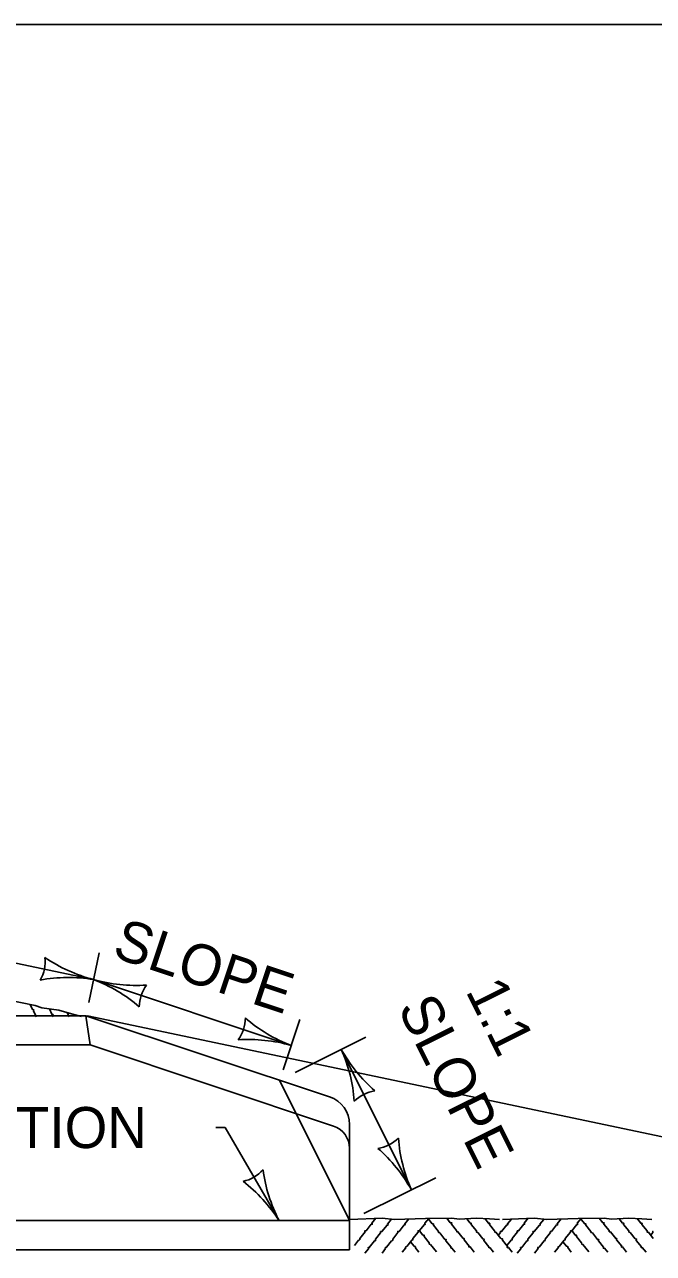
# Model space of a CAD drawing. Extents: x 49991.4 to 50021, y 49987.6 to 50011.4.
# Drawn here: x 50005.853 to 50006.771, y 49997.203 to 49998.999 of the extents above; entities that cross this region are included whole.
import ezdxf

# ---------------------------------------------------------------- set-up
doc = ezdxf.new("R2010")
doc.units = 0
for name, color, linetype in [('Level 1', 7, 'Continuous'), ('Level 2', 7, 'Continuous'), ('Level 3', 7, 'Continuous'), ('Level 4', 7, 'Continuous')]:
    doc.layers.add(name, color=color, linetype=linetype)

msp = doc.modelspace()

# ---------------------------------------------------------------- linework, layer by layer
at = {"layer": 'Level 1'}
for p, q in [((50003.702, 49997.5504), (50005.9421, 49997.5504)), ((50005.9421, 49997.5504), (50006.2981, 49997.4318)), ((50006.3273, 49997.3911), (50006.3273, 49997.208)), ((50006.3273, 49997.208), (50003.702, 49997.208))]:
    msp.add_line(p, q, dxfattribs=at)
msp.add_lwpolyline([(49999.3835, 49998.9992), (50016.7501, 49998.9992), (50016.7501, 49987.7988), (49999.3835, 49987.7988)], close=True, dxfattribs=at)
for points in [[(50005.7214, 49997.5944), (50005.7679, 49997.5866), (50005.785, 49997.5809), (50005.83, 49997.5731), (50005.8678, 49997.5653), (50005.8779, 49997.5617), (50005.9026, 49997.5584), (50005.9212, 49997.5532), (50005.9355, 49997.5494)], [(50005.8697, 49997.5486), (50005.8653, 49997.5572), (50005.866, 49997.559), (50005.8642, 49997.5593), (50005.8606, 49997.5668)], [(50005.8943, 49997.5486), (50005.8935, 49997.5506), (50005.8942, 49997.5522), (50005.8923, 49997.5526), (50005.8888, 49997.5602)], [(50005.9177, 49997.5486), (50005.9146, 49997.5552)], [(50006.3278, 49997.2526), (50006.375, 49997.2545), (50006.3929, 49997.2526), (50006.4385, 49997.2541), (50006.4769, 49997.2543), (50006.4876, 49997.2529), (50006.5126, 49997.2545), (50006.5318, 49997.2535), (50006.5465, 49997.2526)], [(50006.3658, 49997.2543), (50006.3598, 49997.2471), (50006.3605, 49997.2455), (50006.359, 49997.2455), (50006.3516, 49997.2361), (50006.3496, 49997.2361), (50006.35, 49997.2345), (50006.3422, 49997.2249), (50006.3422, 49997.2229), (50006.3406, 49997.2225), (50006.3344, 49997.2145)], [(50006.3882, 49997.2525), (50006.3827, 49997.2459), (50006.3836, 49997.2443), (50006.3821, 49997.2443), (50006.3746, 49997.2349), (50006.3726, 49997.2349), (50006.3728, 49997.2331), (50006.3652, 49997.2235), (50006.3652, 49997.2215), (50006.3636, 49997.2211), (50006.3562, 49997.2115), (50006.3545, 49997.2115), (50006.3548, 49997.2095), (50006.3496, 49997.2033)], [(50006.4139, 49997.2533), (50006.4079, 49997.246), (50006.4086, 49997.2445), (50006.4072, 49997.2445), (50006.3998, 49997.2351), (50006.3977, 49997.2351), (50006.398, 49997.2333), (50006.3905, 49997.2237), (50006.3905, 49997.222), (50006.3887, 49997.2213), (50006.3815, 49997.2119), (50006.3796, 49997.2117), (50006.38, 49997.21), (50006.3748, 49997.2034)], [(50006.4433, 49997.2541), (50006.4373, 49997.2469), (50006.438, 49997.2454), (50006.4367, 49997.2454), (50006.4292, 49997.2361), (50006.4274, 49997.2361), (50006.4276, 49997.2341), (50006.4199, 49997.2245), (50006.4199, 49997.2229), (50006.4182, 49997.2221), (50006.4109, 49997.2129), (50006.4092, 49997.2125), (50006.4094, 49997.2109), (50006.4043, 49997.2045)], [(50006.4817, 49997.2045), (50006.4769, 49997.2107), (50006.4754, 49997.2105), (50006.4757, 49997.2119), (50006.4682, 49997.2211), (50006.4686, 49997.2231), (50006.4667, 49997.2231), (50006.4592, 49997.2329), (50006.4574, 49997.2333), (50006.4572, 49997.2349), (50006.4498, 49997.2443), (50006.4499, 49997.246), (50006.4481, 49997.2461), (50006.443, 49997.2527)], [(50006.5092, 49997.2049), (50006.5036, 49997.2123), (50006.5018, 49997.2119), (50006.5022, 49997.2135), (50006.4948, 49997.2227), (50006.495, 49997.2245), (50006.4934, 49997.2249), (50006.4858, 49997.2345), (50006.4841, 49997.2347), (50006.4838, 49997.2365), (50006.4762, 49997.2459), (50006.4766, 49997.2477), (50006.4746, 49997.2477), (50006.4696, 49997.2543)], [(50006.5378, 49997.2045), (50006.5322, 49997.2115), (50006.5308, 49997.2113), (50006.531, 49997.2125), (50006.5236, 49997.222), (50006.524, 49997.2239), (50006.522, 49997.2241), (50006.5146, 49997.2335), (50006.5128, 49997.234), (50006.5126, 49997.2359), (50006.5051, 49997.2451), (50006.5052, 49997.2469), (50006.5036, 49997.2469), (50006.4985, 49997.2535)], [(50006.5483, 49997.2249), (50006.5412, 49997.2339), (50006.5396, 49997.2341), (50006.5393, 49997.2359), (50006.5316, 49997.2453), (50006.5321, 49997.2471), (50006.5302, 49997.2471), (50006.5249, 49997.2539)], [(50006.5639, 49997.2531), (50006.5579, 49997.246), (50006.5586, 49997.2445), (50006.5572, 49997.2445), (50006.5496, 49997.2351), (50006.5488, 49997.2351)], [(50006.5506, 49997.2526), (50006.5978, 49997.2545), (50006.6156, 49997.2526), (50006.6612, 49997.2541), (50006.6996, 49997.2543), (50006.7103, 49997.2529), (50006.7352, 49997.2545), (50006.7544, 49997.2535), (50006.7692, 49997.2526)], [(50006.5885, 49997.2543), (50006.5825, 49997.2471), (50006.5832, 49997.2455), (50006.5818, 49997.2455), (50006.5744, 49997.2361), (50006.5723, 49997.2361), (50006.5728, 49997.2345), (50006.5651, 49997.2249), (50006.5651, 49997.2229), (50006.5633, 49997.2225), (50006.5573, 49997.2145)], [(50006.611, 49997.2525), (50006.6056, 49997.2459), (50006.606, 49997.2443), (50006.6047, 49997.2443), (50006.5972, 49997.2349), (50006.5954, 49997.2349), (50006.5956, 49997.2331), (50006.5879, 49997.2235), (50006.5879, 49997.2215), (50006.5864, 49997.2211), (50006.579, 49997.2115), (50006.5772, 49997.2115), (50006.5776, 49997.2095), (50006.5723, 49997.2033)], [(50006.6366, 49997.2533), (50006.6306, 49997.246), (50006.6314, 49997.2445), (50006.6299, 49997.2445), (50006.6224, 49997.2351), (50006.6206, 49997.2351), (50006.6209, 49997.2333), (50006.6131, 49997.2237), (50006.6131, 49997.222), (50006.6116, 49997.2213), (50006.6042, 49997.2119), (50006.6023, 49997.2117), (50006.6028, 49997.21), (50006.5975, 49997.2034)], [(50006.666, 49997.2541), (50006.66, 49997.2469), (50006.6608, 49997.2454), (50006.6596, 49997.2454), (50006.6521, 49997.2361), (50006.6502, 49997.2361), (50006.6503, 49997.2341), (50006.6426, 49997.2245), (50006.6426, 49997.2229), (50006.641, 49997.2221), (50006.6336, 49997.2129), (50006.632, 49997.2125), (50006.6323, 49997.2109), (50006.627, 49997.2045)], [(50006.7046, 49997.2045), (50006.6998, 49997.2107), (50006.6982, 49997.2105), (50006.6986, 49997.2119), (50006.6911, 49997.2211), (50006.6914, 49997.2231), (50006.6896, 49997.2231), (50006.6821, 49997.2329), (50006.6803, 49997.2333), (50006.68, 49997.2349), (50006.6725, 49997.2443), (50006.6728, 49997.246), (50006.671, 49997.2461), (50006.6659, 49997.2527)], [(50006.7318, 49997.2049), (50006.7262, 49997.2123), (50006.7246, 49997.2119), (50006.725, 49997.2135), (50006.7175, 49997.2227), (50006.7178, 49997.2245), (50006.7162, 49997.2249), (50006.7085, 49997.2345), (50006.7067, 49997.2347), (50006.7066, 49997.2365), (50006.6989, 49997.2459), (50006.6992, 49997.2477), (50006.6974, 49997.2477), (50006.6923, 49997.2543)], [(50006.7606, 49997.2045), (50006.755, 49997.2115), (50006.7535, 49997.2113), (50006.7538, 49997.2125), (50006.7463, 49997.222), (50006.7468, 49997.2239), (50006.7448, 49997.2241), (50006.7373, 49997.2335), (50006.7355, 49997.234), (50006.7352, 49997.2359), (50006.7277, 49997.2451), (50006.7282, 49997.2469), (50006.7262, 49997.2469), (50006.7212, 49997.2535)], [(50006.771, 49997.2249), (50006.764, 49997.2339), (50006.7622, 49997.2341), (50006.762, 49997.2359), (50006.7544, 49997.2453), (50006.7547, 49997.2471), (50006.7529, 49997.2471), (50006.7475, 49997.2539)], [(50006.4542, 49997.2053), (50006.4456, 49997.2161), (50006.4439, 49997.2166), (50006.4438, 49997.2184), (50006.4362, 49997.2275), (50006.4364, 49997.2295), (50006.4346, 49997.2295), (50006.4296, 49997.2359)], [(50006.5486, 49997.2351), (50006.5476, 49997.2351), (50006.5477, 49997.2333), (50006.545, 49997.2297)], [(50006.677, 49997.2053), (50006.6683, 49997.2161), (50006.6666, 49997.2166), (50006.6665, 49997.2184), (50006.659, 49997.2275), (50006.6592, 49997.2295), (50006.6572, 49997.2295), (50006.6524, 49997.2359)], [(50006.7712, 49997.2351), (50006.7703, 49997.2351), (50006.7706, 49997.2333), (50006.7678, 49997.2297)], [(50006.4286, 49997.2047), (50006.4232, 49997.2115), (50006.4235, 49997.2131), (50006.4216, 49997.2135), (50006.4166, 49997.2199)], [(50006.5648, 49997.2046), (50006.5594, 49997.2117), (50006.5578, 49997.2113), (50006.558, 49997.2129), (50006.5506, 49997.2221), (50006.551, 49997.2241), (50006.5492, 49997.2243), (50006.5488, 49997.2249)], [(50006.6512, 49997.2047), (50006.6461, 49997.2115), (50006.6462, 49997.2131), (50006.6443, 49997.2135), (50006.6392, 49997.2199)]]:
    msp.add_lwpolyline(points, dxfattribs=at)
msp.add_arc((50006.2846, 49997.3912), 0.0428, 0, 71.5416, dxfattribs=at)
at = {"layer": 'Level 2'}
msp.add_line((50016.7501, 49998.9992), (49999.3835, 49998.9992), dxfattribs=at)
at = {"layer": 'Level 3'}
for p, q in [((50004.9341, 49997.8179), (50005.9533, 49997.6033)), ((50005.9462, 49997.5698), (50005.9616, 49997.6424)), ((50006.242, 49997.507), (50005.9533, 49997.6033)), ((50006.2547, 49997.5449), (50006.2301, 49997.4714)), ((50006.2479, 49997.4675), (50006.3511, 49997.519)), ((50006.3153, 49997.5011), (50006.4177, 49997.2958)), ((50006.132, 49997.3869), (50006.1458, 49997.3869)), ((50006.1458, 49997.3869), (50006.2244, 49997.2508)), ((50006.348, 49997.2611), (50006.4535, 49997.3136))]:
    msp.add_line(p, q, dxfattribs=at)
for centre, radius, start, end in [((50005.8278, 49997.6297), 0.0548, 330.2525, 5.9749), ((50006.008, 49997.8188), 0.2223, 235.5697, 255.7532), ((50005.9166, 49997.3732), 0.233, 80.941, 100.1908), ((50005.8743, 49997.3954), 0.2223, 49.0151, 69.1986), ((50006.016, 49997.8277), 0.233, 254.3864, 273.6363), ((50006.0749, 49997.5627), 0.0548, 143.6979, 179.4203), ((50006.1204, 49997.5476), 0.0548, 323.6979, 359.4203), ((50006.321, 49997.7148), 0.2223, 229.0151, 249.1986), ((50006.1793, 49997.2826), 0.233, 74.3864, 93.6363), ((50006.1124, 49997.4102), 0.2223, 3.9652, 24.1487), ((50006.5184, 49997.6153), 0.233, 209.3365, 228.5864), ((50006.3725, 49997.3864), 0.0548, 98.648, 134.3704), ((50006.3605, 49997.4105), 0.0548, 278.648, 314.3704), ((50006.6206, 49997.3868), 0.2223, 183.9652, 204.1487), ((50006.2146, 49997.1817), 0.233, 29.3365, 48.5864), ((50006.1603, 49997.3618), 0.0548, 282.1378, 317.8602), ((50006.4214, 49997.3539), 0.2223, 187.455, 207.6385), ((50006.0286, 49997.1245), 0.233, 32.8263, 52.0762)]:
    msp.add_arc(centre, radius, start, end, dxfattribs=at)
at = {"layer": 'Level 4'}
for p, q in [((50005.9421, 49997.5504), (50005.9483, 49997.5077)), ((50005.9442, 49997.55), (50007.3483, 49997.2547)), ((50003.702, 49997.5077), (50005.9483, 49997.5077)), ((50005.9483, 49997.5077), (50006.304, 49997.3891)), ((50006.2251, 49997.4561), (50006.3273, 49997.2508)), ((50003.702, 49997.2508), (50006.3273, 49997.2508))]:
    msp.add_line(p, q, dxfattribs=at)
msp.add_arc((50006.2931, 49997.3566), 0.0342, 0, 71.5749, dxfattribs=at)

# ---------------------------------------------------------------- texts
at = {"layer": 'Level 2'}
for s, rotation, p in [('SLOPE', 341.5752, (50005.9786, 49997.637)), (' 1:1', 296.4886, (50006.4863, 49997.6065)), ('SLOPE', 296.4886, (50006.3968, 49997.5619))]:
    msp.add_text(s, height=0.06, rotation=rotation, dxfattribs=at).set_placement(p)
msp.add_text('END SECTION', height=0.06, dxfattribs=at).set_placement((50005.483, 49997.3569))

doc.saveas('drawing.dxf')
